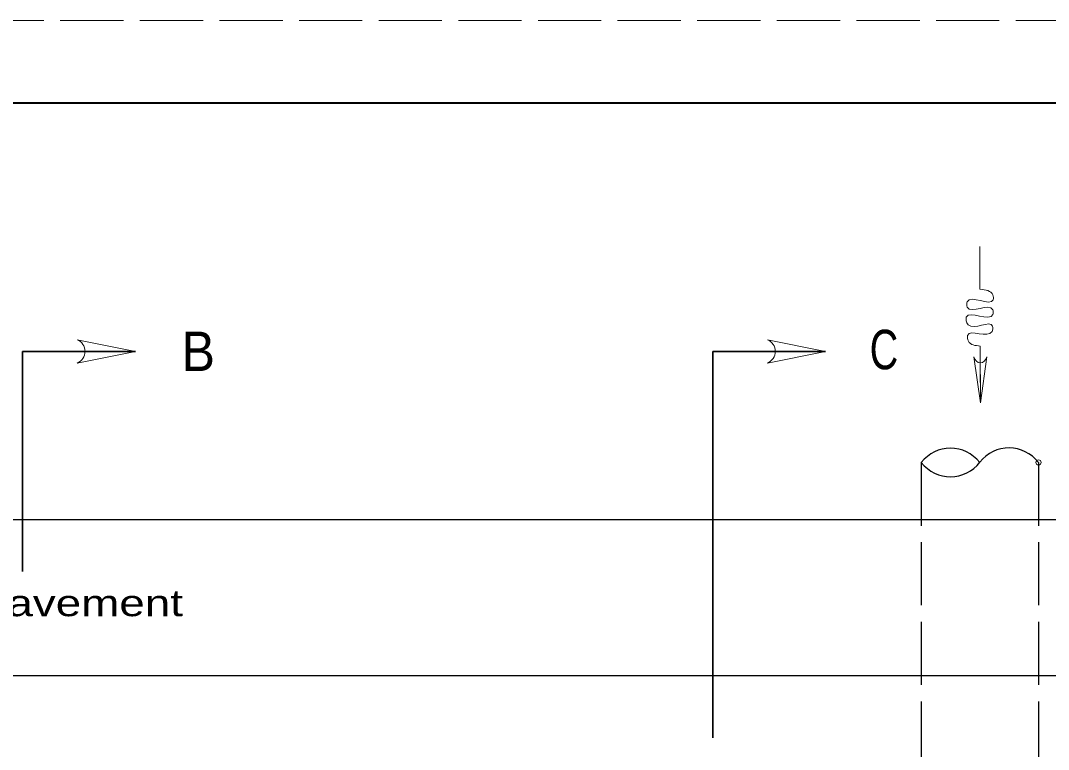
# Model space of a CAD drawing. Extents: x 1043.1 to 1101.1, y 672.4 to 716.4.
# Drawn here: x 1049.41 to 1055.66, y 711.97 to 716.4 of the extents above; entities that cross this region are included whole.
import ezdxf
from ezdxf.enums import TextEntityAlignment as Align

# ---------------------------------------------------------------- set-up
doc = ezdxf.new("R2010")
doc.units = 0
doc.header["$LTSCALE"] = 0.064
doc.header["$PDMODE"] = 32
doc.header["$PDSIZE"] = 0.032
doc.linetypes.add('LONG_DASHED', pattern=[7.5, 6, -1.5])
doc.layers.add('1', color=7, linetype='Continuous', lineweight=13)

msp = doc.modelspace()

# ---------------------------------------------------------------- linework, layer by layer
at = {"layer": '1', "lineweight": 25}
for p, q in [((1045.14425, 715.89508), (1076.64425, 715.89508)), ((1047.132, 713.36458), (1056.394, 713.36458)), ((1047.132, 712.41483), (1056.394, 712.41483))]:
    msp.add_line(p, q, dxfattribs=at)
at = {"layer": '1', "lineweight": 40}
msp.add_line((1045.14425, 715.89508), (1076.64425, 715.89508), dxfattribs=at)
at = {"layer": '1'}
for p, q in [((1055.24683, 714.76258), (1055.2455, 715.02192)), ((1055.25, 714.07192), (1055.2485, 714.4175)), ((1055.24883, 714.31475), (1055.25, 714.07192)), ((1055.24908, 714.24475), (1055.25, 714.07192))]:
    msp.add_line(p, q, dxfattribs=at)
at = {"layer": '1', "lineweight": 35}
for p, q in [((1049.42775, 714.38483), (1050.11308, 714.38483)), ((1049.42775, 713.04683), (1049.42775, 714.38483)), ((1053.62333, 712.03625), (1053.62333, 714.38483)), ((1053.62333, 714.38483), (1054.30867, 714.38483))]:
    msp.add_line(p, q, dxfattribs=at)
at = {"layer": '1', "linetype": 'LONG_DASHED', "lineweight": 25}
for p, q in [((1054.88983, 713.71008), (1054.88983, 711.10542)), ((1055.6025, 713.71008), (1055.6025, 709.6515))]:
    msp.add_line(p, q, dxfattribs=at)
at = {"layer": '1', "linetype": 'LONG_DASHED'}
msp.add_lwpolyline([(1043.14425, 694.39508), (1077.14425, 694.39508), (1077.14425, 716.39508), (1043.14425, 716.39508)], close=True, dxfattribs=at)
at = {"layer": '1', "lineweight": 40}
msp.add_lwpolyline([(1045.14425, 715.89508), (1076.64425, 715.89508), (1076.64425, 694.89508), (1045.14425, 694.89508)], close=True, dxfattribs=at)
at = {"layer": '1'}
for points in [[(1049.75908, 714.45567), (1050.11308, 714.38483), (1049.75908, 714.31408), (1049.75917, 714.31417)], [(1053.95467, 714.45567), (1054.30867, 714.38483), (1053.95467, 714.31408), (1053.95475, 714.31417)], [(1055.28825, 714.35283), (1055.25, 714.07192), (1055.20908, 714.35242), (1055.20908, 714.35233)]]:
    msp.add_lwpolyline(points, dxfattribs=at)
for centre in [(1049.73046, 714.38494), (1053.92604, 714.38494)]:
    msp.add_arc(centre, 0.0764, 292.08605, 67.91218, dxfattribs=at)
msp.add_ellipse((1055.24859, 714.37534), major_axis=(0.00023, -0.06058), ratio=0.705058, start_param=5.0991244, end_param=7.4697376, dxfattribs=at)
at = {"layer": '1', "lineweight": 25}
for centre, start_param, end_param in [((1055.06755, 713.53889), 5.4361787, 7.1303252), ((1055.42326, 713.54076), 5.42643, 7.1303252), ((1055.06755, 713.88128), 2.2944527, 3.9983479)]:
    msp.add_ellipse(centre, major_axis=(0, 0.25855), ratio=0.916763, start_param=start_param, end_param=end_param, dxfattribs=at)
at = {"layer": '1'}
msp.add_spline([(1055.2485, 714.4175), (1055.17608, 714.4465), (1055.1715, 714.4825), (1055.32042, 714.50492), (1055.32375, 714.53825), (1055.17467, 714.54733), (1055.16375, 714.59333), (1055.32533, 714.60858), (1055.32417, 714.638), (1055.16975, 714.65392), (1055.16875, 714.68708), (1055.32667, 714.69875), (1055.3255, 714.72792), (1055.24683, 714.76258)], degree=3, dxfattribs=at)
msp.add_point((1055.6025, 713.71008), dxfattribs=at)

# ---------------------------------------------------------------- texts
for s, width, p in [('B', 0.95, (1050.49517, 714.26533)), ('C', 0.75, (1054.66317, 714.27633))]:
    msp.add_text(s, height=0.24, dxfattribs=dict(at, width=width)).set_placement(p, align=Align.CENTER)
at = {"layer": '1', "width": 1.3}
msp.add_text('Proposed pavement', height=0.16, dxfattribs=at).set_placement((1047.91242, 712.77608))

doc.saveas('drawing.dxf')
